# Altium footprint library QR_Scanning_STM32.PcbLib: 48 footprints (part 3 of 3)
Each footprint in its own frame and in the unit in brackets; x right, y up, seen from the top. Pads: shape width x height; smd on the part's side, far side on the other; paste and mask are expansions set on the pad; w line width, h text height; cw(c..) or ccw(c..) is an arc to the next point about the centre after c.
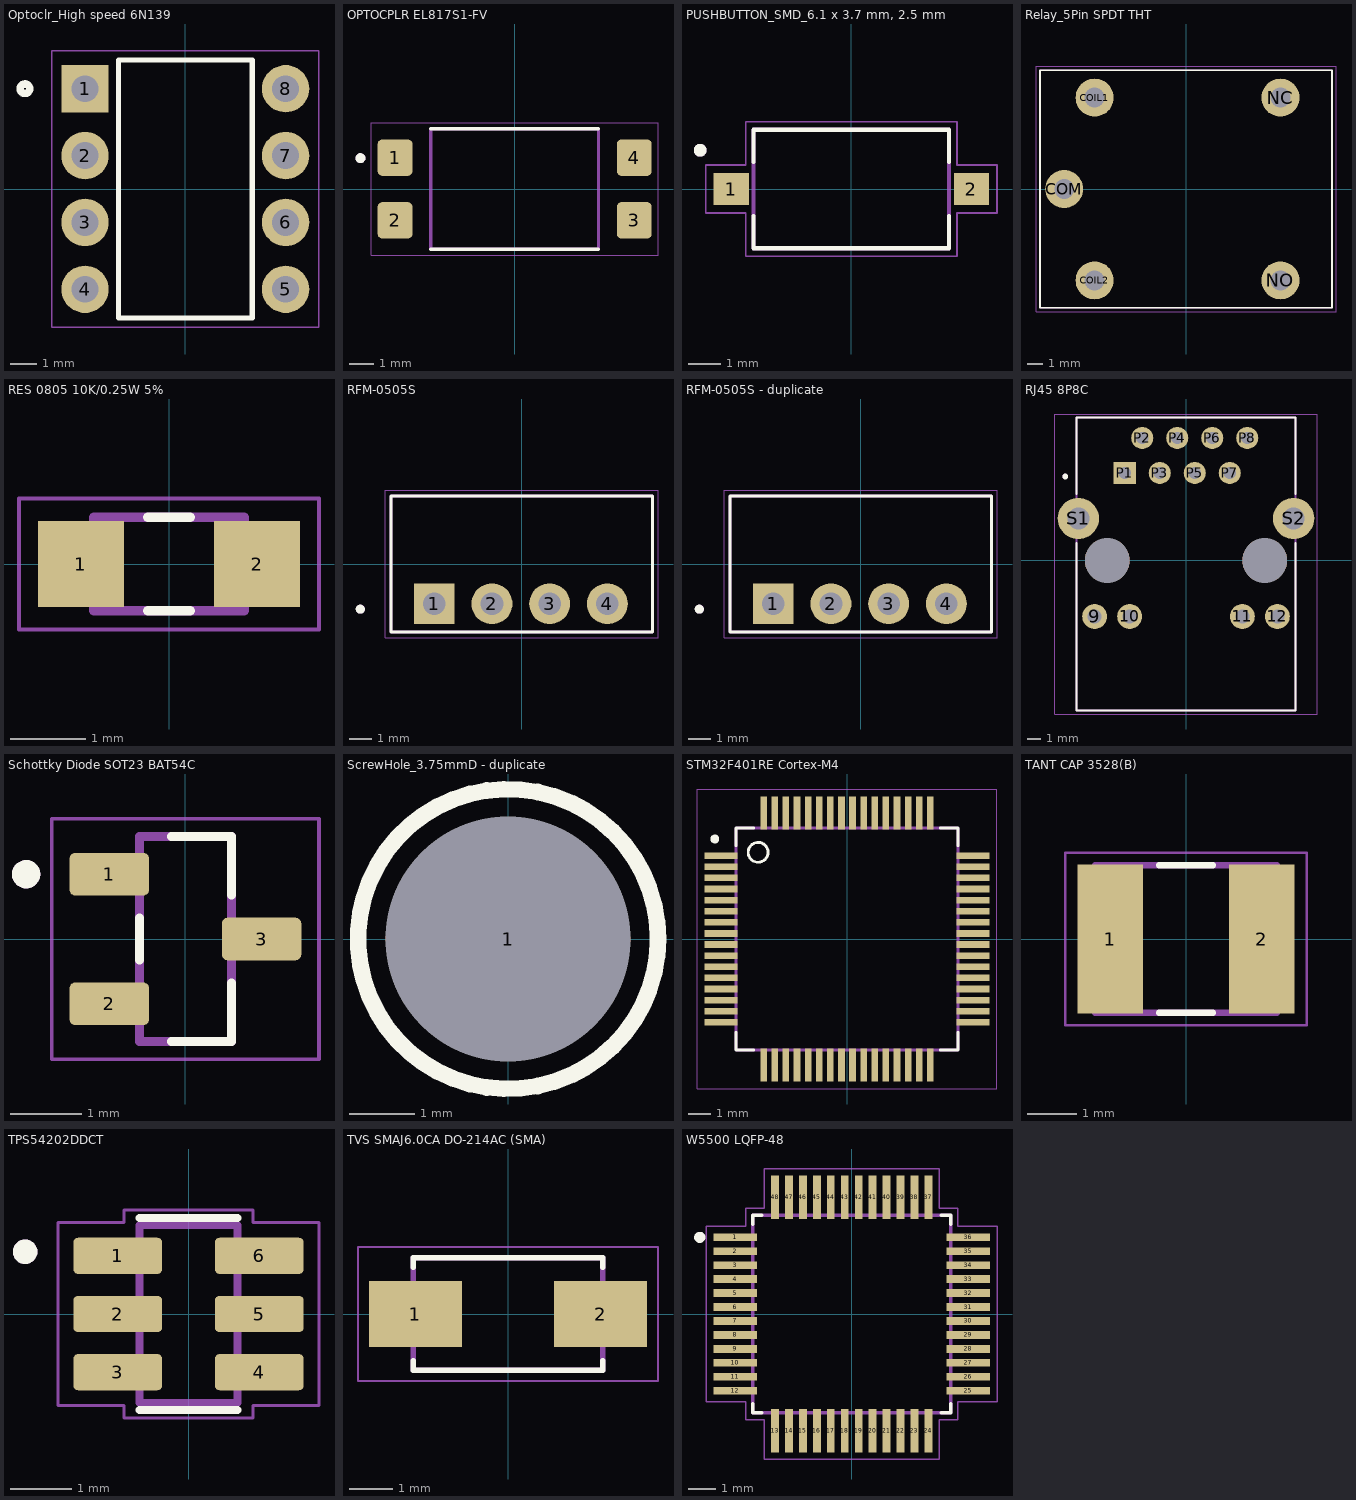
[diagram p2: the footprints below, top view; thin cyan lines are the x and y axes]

## Optoclr_High speed 6N139 [mm] "Optoclr_High speed 6N139 DIP-8"
pads (8):
  rect 1.8x1.8 hole 1.02: 1(-3.81,3.81)
  round 1.8 hole 1.02: 2(-3.81,1.27) 3(-3.81,-1.27) 4(-3.81,-3.81) 5(3.81,-3.81) 6(3.81,-1.27) 7(3.81,1.27) 8(3.81,3.81)
Top Overlay:
  circle w0.2: c-6.096,3.81 r0.141
  circle w0.2: c-6.096,3.81 r0.224
  lines w0.2: -2.54,-4.9 2.54,-4.9 2.54,4.9 -2.54,4.9 -2.54,-4.9
Mechanical 15:
  lines w0.05: -5.08,-5.25 5.08,-5.25 5.08,5.25 -5.08,5.25 -5.08,-5.25
3D body "step_temp.STEP": height 5.08, standoff -3.9, extent -3.96,-4.828 3.96,4.828

## OPTOCPLR EL817S1-FV [mm] "OPTOCPLR EL817S1 SOIC254P1030X390-4N_EL817S1-FV"
pads (4):
  rrect25% 1.41x1.47 smd: 1(-4.85,1.27) 2(-4.85,-1.27) 3(4.85,-1.27) 4(4.85,1.27)
Top Overlay:
  circle w0.2: c-6.25,1.25 r0.1
  lines w0.127: -3.4,-2.44 3.4,-2.44 ; -3.4,2.44 3.4,2.44
Mechanical 13:
  circle w0.2: c-6.25,1.25 r0.1
  lines w0.127: -3.4,-2.44 3.4,-2.44 3.4,2.44 -3.4,2.44 -3.4,-2.44
Mechanical 15:
  lines w0.05: -5.81,-2.69 -5.81,2.69 5.81,2.69 5.81,-2.69 -5.81,-2.69
3D body "EL817S1(C)(TA)-V.STEP": height 3.9, standoff 0, extent -5.023,-2.29 5.277,2.29

## PCBComponent_1 [mm]

## PUSHBUTTON_SMD_6.1 x 3.7 mm, 2.5 mm [mm] "6.1 x 3.7 mm, 2.5 mm Actuator Height, 260 gf, Red, Surface Mount, SPST, Tactile Switch, TS09-63-25-R-260-SMT-TR"
height 2.5
pads (2):
  rect 1.1x1 smd: 1(-3.75,0) 2(3.75,0)
Top Overlay:
  circle w0.2: c-4.72,1.21 r0.1
  lines w0.127: -3.05,-0.85 -3.05,-1.85 3.05,-1.85 3.05,-0.85 ; -3.05,0.85 -3.05,1.85 3.05,1.85 3.05,0.85
Mechanical 13:
  circle w0.2: c-4.72,1.21 r0.1
  lines w0.127: -3.05,-1.85 -3.05,1.85 3.05,1.85 3.05,-1.85 -3.05,-1.85
Mechanical 15:
  lines w0.05: -4.55,-0.75 -3.3,-0.75 -3.3,-2.1 3.3,-2.1 3.3,-0.75 4.55,-0.75 4.55,0.75 3.3,0.75 3.3,2.1 -3.3,2.1 -3.3,0.75 -4.55,0.75 -4.55,-0.75
3D body "step_temp.STEP": height 2.5, standoff -0.05, extent -4.05,-1.85 4.05,1.85

## Relay_5Pin SPDT THT [mm] "Relay_5Pin SPDT THT RELAY_SRD-03VDC-SL-C"
height 15.8
pads (5):
  round 2.5 hole 1.3: COIL1(-6,6) COIL2(-6,-6) COM(-8,0) NC(6.2,6) NO(6.2,-6)
Top Overlay:
  lines w0.127: -9.6,-7.8 -9.6,7.8 9.6,7.8 9.6,-7.8 -9.6,-7.8
Mechanical 13:
  lines w0.127: -9.6,-7.8 -9.6,7.8 9.6,7.8 9.6,-7.8 -9.6,-7.8
Mechanical 15:
  lines w0.05: -9.85,-8.05 -9.85,8.05 9.85,8.05 9.85,-8.05 -9.85,-8.05
3D body "step_temp.STEP": height 15.8, standoff -3, extent -9.6,-7.8 9.6,7.8

## RES 0805 10K/0.25W 5% [mm] "RESISTOR, THICK FILM, 10K, 5%, 0805, SMT FULL REEL Product Range:PANASONIC - ERJ Series"
height 0.55
pads (2):
  rect 1.15x1.15 smd: 1(-1.175,0) 2(1.175,0)
Top Overlay:
  lines w0.127: -0.28,-0.625 0.28,-0.625 ; -0.28,0.625 0.28,0.625
Mechanical 13:
  lines w0.127: -1,-0.625 -1,0.625 1,0.625 1,-0.625 -1,-0.625
Mechanical 15:
  lines w0.05: -2,-0.875 -2,0.875 2,0.875 2,-0.875 -2,-0.875
3D body "step_temp.STEP": height 0.7, standoff 0, extent -1,-0.625 1,0.625

## RFM-0505S [mm] "DC-DC Converter/Isolator, SIP4, THT S/T 1kV unreg, Single Output, 1W, 5V Out, RFM Series RFM-0505S"
height 10
pads (4):
  rect 1.8x1.8 hole 1: 1(-3.85,-1.75)
  round 1.8 hole 1: 2(-1.31,-1.75) 3(1.23,-1.75) 4(3.77,-1.75)
Top Overlay:
  circle w0.2: c-7.11,-1.99 r0.1
  lines w0.127: -5.75,-3 -5.75,3 5.75,3 5.75,-3 -5.75,-3
Mechanical 13:
  circle w0.2: c-7.1,-1.99 r0.1
  lines w0.127: -5.75,-3 -5.75,3 5.75,3 5.75,-3 -5.75,-3
Mechanical 15:
  lines w0.05: -6,-3.25 -6,3.25 6,3.25 6,-3.25 -6,-3.25
3D body "step_temp.STEP": height 9.5, standoff -4.6, extent -5.75,-3 5.75,3

## RFM-0505S - duplicate [mm] "DC-DC Converter/Isolator, SIP4, THT S/T 1kV unreg, Single Output, 1W, 5V Out, RFM Series RFM-0505S"
height 10
pads (4):
  rect 1.8x1.8 hole 1: 1(-3.85,-1.75)
  round 1.8 hole 1: 2(-1.31,-1.75) 3(1.23,-1.75) 4(3.77,-1.75)
Top Overlay:
  circle w0.2: c-7.11,-1.99 r0.1
  lines w0.127: -5.75,-3 -5.75,3 5.75,3 5.75,-3 -5.75,-3
Mechanical 13:
  circle w0.2: c-7.1,-1.99 r0.1
  lines w0.127: -5.75,-3 -5.75,3 5.75,3 5.75,-3 -5.75,-3
Mechanical 15:
  lines w0.05: -6,-3.25 -6,3.25 6,3.25 6,-3.25 -6,-3.25
3D body "step_temp.STEP": height 9.5, standoff -4.6, extent -5.75,-3 5.75,3

## RJ45 8P8C [mm] "RJ45 8P8C CUI_CRJ011-ML1-TH"
height 13.6
pads (16):
  round 1.808 hole 1: 9(-6.63,-4.06) 10(-4.09,-4.06) 11(4.09,-4.06) 12(6.63,-4.06)
  rect 1.608x1.608 hole 0.9: P1(-4.445,6.35)
  round 1.608 hole 0.9: P2(-3.175,8.89) P3(-1.905,6.35) P4(-0.635,8.89) P5(0.635,6.35) P6(1.905,8.89) P7(3.175,6.35) P8(4.445,8.89)
  round 3 hole 1.6: S1(-7.815,3.05) S2(7.815,3.05)
  round 3.25 hole 3.25 unplated: ""(-5.715,0) ""(5.715,0)
Top Overlay:
  circle w0.2: c-8.763,6.096 r0.111
  lines w0.127: -7.94,1.27 -7.94,-10.89 7.94,-10.89 7.94,1.27 ; -7.94,4.826 -7.94,10.38 7.94,10.38 7.94,4.826
Mechanical 13:
  circle w0.2: c-8.763,6.096 r0.1
  lines w0.127: -7.94,-10.89 7.94,-10.89 7.94,10.38 -7.94,10.38 -7.94,-10.89
Mechanical 15:
  lines w0.05: -9.525,-11.14 -9.525,10.63 9.525,10.63 9.525,-11.14 -9.525,-11.14
3D body "step_temp.STEP": height 13.3, standoff -3.74, extent -8.34,-10.922 8.34,10.345

## Schottky Diode SOT23 BAT54C [mm] "Schottky Diode SOT23 BAT54C"
height 1.15
pads (3):
  rrect25% 1.12x0.6 smd: 1(-1.075,0.915) 2(-1.075,-0.915) 3(1.075,0)
Top Overlay:
  circle w0.2: c-2.25,0.915 r0.1
  lines w0.127: -0.65,-0.295 -0.65,0.295 ; -0.195,-1.45 0.65,-1.45 0.65,-0.62 ; -0.195,1.45 0.65,1.45 0.65,0.62
Mechanical 13:
  circle w0.2: c-2.25,0.915 r0.1
  lines w0.127: -0.65,-1.45 -0.65,1.45 0.65,1.45 0.65,-1.45 -0.65,-1.45
Mechanical 15:
  lines w0.05: -1.885,-1.7 -1.885,1.7 1.885,1.7 1.885,-1.7 -1.885,-1.7
3D body "step_temp.STEP": height 1.14, standoff 0, extent -1.2,-1.45 1.2,1.45

## ScrewHole_3.75mmD - duplicate [mm] "SCREW HEAD DIA 4.5MM, SREW LEG DIA 3 MM"
pads (1):
  round 3.75 hole 3.75 unplated: 1(0,0)
Top Overlay:
  circle w0.254: c0,0 r2.3

## STM32F401RE Cortex-M4 [mm] "ARMÂ® CortexÂ®-M4 STM32F4 Microcontroller IC 32-Bit Single-Core 84MHz 512KB (512K x 8) FLASH 64-LQFP (10x10)"
pads (64):
  rect 1.5x0.3 smd: 1(-5.67,3.75) 2(-5.67,3.25) 3(-5.67,2.75) 4(-5.67,2.25) 5(-5.67,1.75) 6(-5.67,1.25) 7(-5.67,0.75) 8(-5.67,0.25) 9(-5.67,-0.25) 10(-5.67,-0.75) 11(-5.67,-1.25) 12(-5.67,-1.75) 13(-5.67,-2.25) 14(-5.67,-2.75) 15(-5.67,-3.25) 16(-5.67,-3.75) 33(5.67,-3.75) 34(5.67,-3.25) 35(5.67,-2.75) 36(5.67,-2.25) 37(5.67,-1.75) 38(5.67,-1.25) 39(5.67,-0.75) 40(5.67,-0.25) 41(5.67,0.25) 42(5.67,0.75) 43(5.67,1.25) 44(5.67,1.75) 45(5.67,2.25) 46(5.67,2.75) 47(5.67,3.25) 48(5.67,3.75)
  rect 0.3x1.5 smd: 17(-3.75,-5.67) 18(-3.25,-5.67) 19(-2.75,-5.67) 20(-2.25,-5.67) 21(-1.75,-5.67) 22(-1.25,-5.67) 23(-0.75,-5.67) 24(-0.25,-5.67) 25(0.25,-5.67) 26(0.75,-5.67) 27(1.25,-5.67) 28(1.75,-5.67) 29(2.25,-5.67) 30(2.75,-5.67) 31(3.25,-5.67) 32(3.75,-5.67) 49(3.75,5.67) 50(3.25,5.67) 51(2.75,5.67) 52(2.25,5.67) 53(1.75,5.67) 54(1.25,5.67) 55(0.75,5.67) 56(0.25,5.67) 57(-0.25,5.67) 58(-0.75,5.67) 59(-1.25,5.67) 60(-1.75,5.67) 61(-2.25,5.67) 62(-2.75,5.67) 63(-3.25,5.67) 64(-3.75,5.67)
Top Overlay:
  circle w0.2: c-5.95,4.5 r0.1
  circle w0.127: c-4,3.9 r0.447
  lines w0.127: -5,-4.2 -5,-5 -4.2,-5 ; -5,4.2 -5,5 -4.2,5 ; 4.2,-5 5,-5 5,-4.2 ; 4.2,5 5,5 5,4.2
Mechanical 13:
  lines w0.127: -5,-5 -5,5 5,5 5,-5 -5,-5
Mechanical 15:
  lines w0.05: -6.75,-6.75 -6.75,6.75 6.75,6.75 6.75,-6.75 -6.75,-6.75
3D body "step_temp.STEP": height 1.6, standoff 0, extent -6,-6 6,6

## TANT CAP 3528(B) [mm] "10 ÂµF Molded Tantalum Polymer Capacitor 25 V 1411 (3528 Metric), 1210 150mOhm TCJB106M025R0150"
pads (2):
  rect 1.34x3.02 smd: 1(-1.54,0) 2(1.54,0)
Top Overlay:
  lines w0.127: -0.55,-1.5 0.55,-1.5 ; -0.55,1.5 0.55,1.5
Mechanical 13:
  lines w0.127: -1.85,-1.5 -1.85,1.5 1.85,1.5 1.85,-1.5 -1.85,-1.5
Mechanical 15:
  lines w0.05: -2.458,-1.75 -2.458,1.75 2.458,1.75 2.458,-1.75 -2.458,-1.75
3D body "step_temp.STEP": height 2.1, standoff 0, extent -1.75,-1.4 1.75,1.4

## TPS54202DDCT [mm] "4.5V to 28V Input, 2A Output, EMI Friendly Synchronous Step-Down Converter SOT23-6"
pads (6):
  rrect25% 1.45x0.59 smd: 1(-1.155,0.95) 2(-1.155,0) 3(-1.155,-0.95) 4(1.155,-0.95) 5(1.155,0) 6(1.155,0.95)
Top Overlay:
  circle w0.2: c-2.667,1.016 r0.1
  lines w0.127: -0.8,-1.565 0.8,-1.565 ; -0.8,1.565 0.8,1.565
Mechanical 13:
  circle w0.2: c-2.667,1.016 r0.1
  lines w0.127: -0.8,-1.45 -0.8,1.45 0.8,1.45 0.8,-1.45 -0.8,-1.45
Mechanical 15:
  lines w0.05: -2.13,-1.495 -2.13,1.495 -1.05,1.495 -1.05,1.7 1.05,1.7 1.05,1.495 2.13,1.495 2.13,-1.495 1.05,-1.495 1.05,-1.7 -1.05,-1.7 -1.05,-1.495 -2.13,-1.495
3D body "step_temp.STEP": height 1.1, standoff 0, extent -1.4,-1.45 1.4,1.45

## TVS SMAJ6.0CA DO-214AC (SMA) [mm] "SMAJ6.0CA WG Bidirectional TVS diode littlefuse DO-214AC (SMA)"
pads (2):
  rect 2.12x1.5 smd: 1(-2.115,0) 2(2.115,0)
Top Overlay:
  lines w0.127: -2.165,-1.07 -2.165,-1.28 2.165,-1.28 2.165,-1.07 ; -2.165,1.07 -2.165,1.28 2.165,1.28 2.165,1.07
Mechanical 13:
  lines w0.127: -2.165,-1.28 2.165,-1.28 2.165,1.28 -2.165,1.28 -2.165,-1.28
Mechanical 15:
  lines w0.05: -3.425,-1.53 3.425,-1.53 3.425,1.53 -3.425,1.53 -3.425,-1.53
3D body "SMAJ5.0A.STEP": height 2.5, standoff 0, extent -2.57,-1.153 2.57,1.407

## W5500 LQFP-48 [mm] "W5500 LQFP-48 Hardwired TCP/IP embedded Ethernet controller QFP50P900X900X160-48N"
pads (48):
  rect 1.56x0.28 smd: 1(-4.18,2.75) 2(-4.18,2.25) 3(-4.18,1.75) 4(-4.18,1.25) 5(-4.18,0.75) 6(-4.18,0.25) 7(-4.18,-0.25) 8(-4.18,-0.75) 9(-4.18,-1.25) 10(-4.18,-1.75) 11(-4.18,-2.25) 12(-4.18,-2.75) 25(4.18,-2.75) 26(4.18,-2.25) 27(4.18,-1.75) 28(4.18,-1.25) 29(4.18,-0.75) 30(4.18,-0.25) 31(4.18,0.25) 32(4.18,0.75) 33(4.18,1.25) 34(4.18,1.75) 35(4.18,2.25) 36(4.18,2.75)
  rect 0.28x1.56 smd: 13(-2.75,-4.18) 14(-2.25,-4.18) 15(-1.75,-4.18) 16(-1.25,-4.18) 17(-0.75,-4.18) 18(-0.25,-4.18) 19(0.25,-4.18) 20(0.75,-4.18) 21(1.25,-4.18) 22(1.75,-4.18) 23(2.25,-4.18) 24(2.75,-4.18) 37(2.75,4.18) 38(2.25,4.18) 39(1.75,4.18) 40(1.25,4.18) 41(0.75,4.18) 42(0.25,4.18) 43(-0.25,4.18) 44(-0.75,4.18) 45(-1.25,4.18) 46(-1.75,4.18) 47(-2.25,4.18) 48(-2.75,4.18)
Top Overlay:
  circle w0.2: c-5.45,2.75 r0.1
  lines w0.127: -3.55,-3.22 -3.55,-3.55 -3.22,-3.55 ; -3.55,3.22 -3.55,3.55 -3.22,3.55 ; 3.22,-3.55 3.55,-3.55 3.55,-3.22 ; 3.22,3.55 3.55,3.55 3.55,3.22
Mechanical 13:
  drawing of 52 lines, arcs and shapes, not listed
Mechanical 15:
  lines w0.05: -5.21,-3.14 -3.8,-3.14 -3.8,-3.8 -3.14,-3.8 -3.14,-5.21 3.14,-5.21 3.14,-3.8 3.8,-3.8 3.8,-3.14 5.21,-3.14 5.21,3.14 3.8,3.14 3.8,3.8 3.14,3.8 3.14,5.21 -3.14,5.21 -3.14,3.8 -3.8,3.8 -3.8,3.14 -5.21,3.14 -5.21,-3.14
3D body "W5500--3DModel-STEP-56544.STEP": height 1.6, standoff 0, extent -4.5,-4.5 4.5,4.5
